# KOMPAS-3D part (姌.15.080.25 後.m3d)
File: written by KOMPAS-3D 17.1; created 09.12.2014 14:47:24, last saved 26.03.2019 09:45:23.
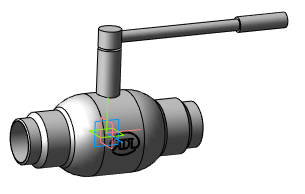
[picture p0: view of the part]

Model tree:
1. Операция без истории:5  (labels: Сталь 20  ГОСТ 1050-88)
